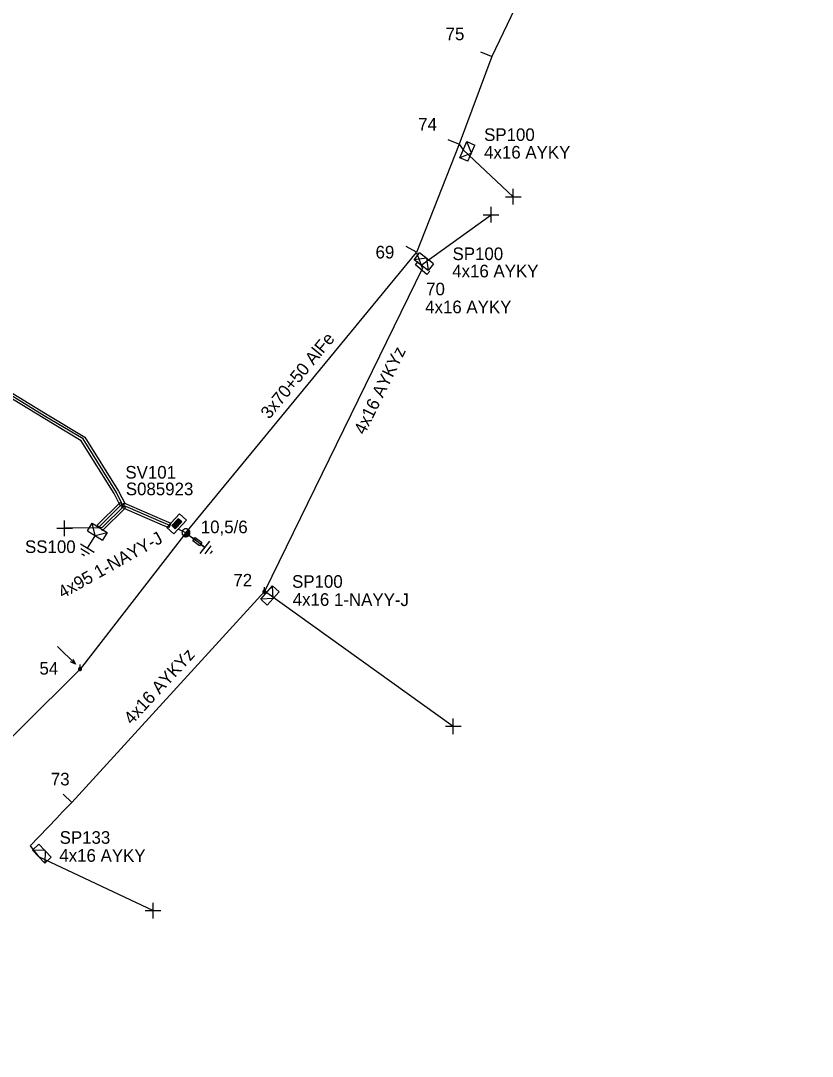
# Model space of a CAD drawing. Extents: x -788458 to -786145, y -1154772 to -1152372.
# Drawn here: x -787255.2 to -787192.5, y -1152639.6 to -1152557.4 of the extents above; entities that cross this region are included whole.
import ezdxf

# ---------------------------------------------------------------- set-up
doc = ezdxf.new("R2010")
doc.units = 0
for name, color, linetype in [('Vrstva 1', 7, 'Continuous'), ('Vrstva 12', 7, 'Continuous'), ('Vrstva 13', 7, 'Continuous'), ('Vrstva 14', 7, 'Continuous'), ('Vrstva 15', 7, 'Continuous'), ('Vrstva 16', 7, 'Continuous'), ('Vrstva 2', 7, 'Continuous'), ('Vrstva 20', 7, 'Continuous'), ('Vrstva 28', 7, 'Continuous'), ('Vrstva 29', 7, 'Continuous'), ('Vrstva 30', 7, 'Continuous'), ('Vrstva 31', 7, 'Continuous'), ('Vrstva 33', 7, 'Continuous'), ('Vrstva 34', 7, 'Continuous'), ('Vrstva 5', 7, 'Continuous'), ('Vrstva 52', 7, 'Continuous'), ('Vrstva 53', 7, 'Continuous'), ('Vrstva 54', 7, 'Continuous'), ('Vrstva 55', 7, 'Continuous'), ('Vrstva 59', 7, 'Continuous'), ('Vrstva 6', 7, 'Continuous'), ('Vrstva 8', 7, 'Continuous'), ('Vrstva 9', 7, 'Continuous')]:
    doc.layers.add(name, color=color, linetype=linetype)

# ---------------------------------------------------------------- blocks, each defined once
blk = doc.blocks.new('NN440')
at = {"layer": 'Vrstva 2'}
for points in [[(0.63, 0), (0.63, 0.06), (0.62, 0.13), (0.6, 0.19), (0.58, 0.25), (0.55, 0.31), (0.51, 0.37), (0.47, 0.42), (0.42, 0.46), (0.37, 0.51), (0.32, 0.54), (0.26, 0.57), (0.2, 0.59), (0.13, 0.61), (0.07, 0.62), (0, 0.63), (-0.06, 0.62), (-0.13, 0.61), (-0.19, 0.59), (-0.26, 0.57), (-0.31, 0.54), (-0.37, 0.51), (-0.42, 0.46), (-0.47, 0.42), (-0.51, 0.37), (-0.54, 0.31), (-0.57, 0.25), (-0.6, 0.19), (-0.62, 0.13), (-0.63, 0.06), (-0.63, 0), (-0.63, -0.07), (-0.62, -0.14), (-0.6, -0.2), (-0.57, -0.26), (-0.54, -0.32), (-0.51, -0.37), (-0.47, -0.43), (-0.42, -0.47), (-0.37, -0.51), (-0.31, -0.55), (-0.26, -0.58), (-0.19, -0.6), (-0.13, -0.62), (-0.06, -0.63), (0, -0.63), (0.07, -0.63), (0.13, -0.62), (0.2, -0.6), (0.26, -0.58), (0.32, -0.55), (0.37, -0.51), (0.42, -0.47), (0.47, -0.43), (0.51, -0.37), (0.55, -0.32), (0.58, -0.26), (0.6, -0.2), (0.62, -0.14), (0.63, -0.07), (0.63, 0)], [(-0.63, 0), (0.63, 0)], [(-0.6, -0.18), (0.57, -0.18)], [(-0.51, -0.32), (0.5, -0.32)], [(-0.37, -0.47), (0.35, -0.47)]]:
    blk.add_lwpolyline(points, dxfattribs=at)
blk = doc.blocks.new('NN565')
at = {"layer": 'Vrstva 2'}
for points in [[(0.015, 0.528), (0.015, 2.528)], [(0.157, 0.937), (0.015, 0.528), (-0.119, 0.937)]]:
    blk.add_lwpolyline(points, dxfattribs=at)
blk = doc.blocks.new('NN800')
at = {"layer": 'Vrstva 1'}
for points in [[(-0.442, 0.442), (0.442, -0.442)], [(-0.442, -0.442), (0.442, 0.442)]]:
    blk.add_lwpolyline(points, dxfattribs=at)
blk = doc.blocks.new('NN820')
at = {"layer": 'Vrstva 13'}
for points in [[(-0.003, 0.004), (-0.003, -1.049)], [(-0.165, -0.813), (0.165, -0.813)], [(-0.165, -1.473), (-0.165, -0.813)], [(0.165, -0.813), (0.165, -1.473)], [(0.165, -1.473), (-0.165, -1.473)], [(-0.003, -1.049), (-0.062, -0.926)], [(-0.003, -1.049), (0.057, -0.926)], [(-0.003, -1.473), (-0.003, -1.871)]]:
    blk.add_lwpolyline(points, dxfattribs=at)
blk = doc.blocks.new('NN620')
at = {"layer": 'Vrstva 8'}
for points in [[(0.752, 0.004), (-0.748, 0.004)], [(-0.748, 0.004), (-0.748, -0.746)], [(0.752, -0.746), (0.752, 0.004)], [(-0.748, -0.746), (0.752, -0.746)], [(0.368, -0.18), (-0.376, -0.18)], [(-0.376, -0.18), (-0.376, -0.558)], [(-0.376, -0.558), (0.368, -0.558)], [(0.321, -0.227), (-0.329, -0.227)], [(-0.329, -0.227), (-0.329, -0.51)], [(-0.329, -0.51), (0.321, -0.51)], [(0.274, -0.274), (-0.281, -0.274)], [(-0.281, -0.274), (-0.281, -0.463)], [(-0.281, -0.463), (0.274, -0.463)], [(0.227, -0.321), (-0.234, -0.321)], [(-0.234, -0.321), (-0.234, -0.416)], [(-0.234, -0.416), (0.227, -0.416)], [(-0.193, -0.369), (0.185, -0.369)], [(0.227, -0.416), (0.227, -0.321)], [(0.274, -0.463), (0.274, -0.274)], [(0.321, -0.51), (0.321, -0.227)], [(0.368, -0.558), (0.368, -0.18)]]:
    blk.add_lwpolyline(points, dxfattribs=at)
blk = doc.blocks.new('NN630')
at = {"layer": 'Vrstva 9'}
for points in [[(-0.003, -0.7), (-0.703, 0)], [(-0.703, -0.7), (-0.703, 0), (0.697, 0), (0.697, -0.7)], [(-0.703, -0.7), (0.697, -0.7)], [(-0.003, -0.7), (0.697, 0)]]:
    blk.add_lwpolyline(points, dxfattribs=at)
blk = doc.blocks.new('NN810')
at = {"layer": 'Vrstva 14'}
for points in [[(0.004, -0.64), (0.004, -1.89)], [(0.629, -1.89), (-0.621, -1.89)], [(0.388, -2.2), (-0.399, -2.2)], [(0.004, -2.515), (-0.124, -2.515)], [(0.137, -2.515), (0.004, -2.515)]]:
    blk.add_lwpolyline(points, dxfattribs=at)
blk = doc.blocks.new('NN500')
at = {"layer": 'Vrstva 2'}
for points in [[(0, -0.24), (0.02, -0.23), (0.05, -0.23), (0.07, -0.22), (0.09, -0.22), (0.12, -0.2), (0.14, -0.19), (0.16, -0.18), (0.17, -0.16), (0.19, -0.14), (0.2, -0.12), (0.21, -0.1), (0.22, -0.07), (0.23, -0.05), (0.23, -0.02), (0.23, 0), (0.23, 0.02), (0.23, 0.05), (0.22, 0.07), (0.21, 0.1), (0.2, 0.12), (0.19, 0.14), (0.17, 0.16), (0.16, 0.17), (0.14, 0.19), (0.12, 0.2), (0.09, 0.21), (0.07, 0.22), (0.05, 0.23), (0.02, 0.23), (0, 0.23), (-0.03, 0.23), (-0.05, 0.23), (-0.07, 0.22), (-0.1, 0.21), (-0.12, 0.2), (-0.14, 0.19), (-0.16, 0.17), (-0.18, 0.16), (-0.19, 0.14), (-0.2, 0.12), (-0.22, 0.1), (-0.22, 0.07), (-0.23, 0.05), (-0.23, 0.02), (-0.24, 0), (-0.23, -0.02), (-0.23, -0.05), (-0.22, -0.07), (-0.22, -0.1), (-0.2, -0.12), (-0.19, -0.14), (-0.18, -0.16), (-0.16, -0.18), (-0.14, -0.19), (-0.12, -0.2), (-0.1, -0.22), (-0.07, -0.22), (-0.05, -0.23), (-0.03, -0.23), (0, -0.24)], [(0, -0.24), (0.02, -0.23), (0.05, -0.23), (0.07, -0.22), (0.09, -0.22), (0.12, -0.2), (0.14, -0.19), (0.16, -0.18), (0.17, -0.16), (0.19, -0.14), (0.2, -0.12), (0.21, -0.1), (0.22, -0.07), (0.23, -0.05), (0.23, -0.02), (0.23, 0), (0.23, 0.02), (0.23, 0.05), (0.22, 0.07), (0.21, 0.1), (0.2, 0.12), (0.19, 0.14), (0.17, 0.16), (0.16, 0.17), (0.14, 0.19), (0.12, 0.2), (0.09, 0.21), (0.07, 0.22), (0.05, 0.23), (0.02, 0.23), (0, 0.23), (-0.03, 0.23), (-0.05, 0.23), (-0.07, 0.22), (-0.1, 0.21), (-0.12, 0.2), (-0.14, 0.19), (-0.16, 0.17), (-0.18, 0.16), (-0.19, 0.14), (-0.2, 0.12), (-0.22, 0.1), (-0.22, 0.07), (-0.23, 0.05), (-0.23, 0.02), (-0.24, 0), (-0.23, -0.02), (-0.23, -0.05), (-0.22, -0.07), (-0.22, -0.1), (-0.2, -0.12), (-0.19, -0.14), (-0.18, -0.16), (-0.16, -0.18), (-0.14, -0.19), (-0.12, -0.2), (-0.1, -0.22), (-0.07, -0.22), (-0.05, -0.23), (-0.03, -0.23), (0, -0.24)], [(0, -0.21), (0.02, -0.2), (0.04, -0.2), (0.06, -0.2), (0.08, -0.19), (0.1, -0.18), (0.12, -0.17), (0.14, -0.15), (0.15, -0.14), (0.16, -0.12), (0.18, -0.1), (0.19, -0.08), (0.19, -0.06), (0.2, -0.04), (0.2, -0.02), (0.2, 0), (0.2, 0.02), (0.2, 0.04), (0.19, 0.06), (0.19, 0.08), (0.18, 0.1), (0.16, 0.12), (0.15, 0.14), (0.14, 0.15), (0.12, 0.17), (0.1, 0.18), (0.08, 0.19), (0.06, 0.19), (0.04, 0.2), (0.02, 0.2), (0, 0.2), (-0.02, 0.2), (-0.04, 0.2), (-0.06, 0.19), (-0.08, 0.19), (-0.1, 0.18), (-0.12, 0.17), (-0.14, 0.15), (-0.15, 0.14), (-0.17, 0.12), (-0.18, 0.1), (-0.19, 0.08), (-0.2, 0.06), (-0.2, 0.04), (-0.21, 0.02), (-0.21, 0), (-0.21, -0.02), (-0.2, -0.04), (-0.2, -0.06), (-0.19, -0.08), (-0.18, -0.1), (-0.17, -0.12), (-0.15, -0.14), (-0.14, -0.15), (-0.12, -0.17), (-0.1, -0.18), (-0.08, -0.19), (-0.06, -0.2), (-0.04, -0.2), (-0.02, -0.2), (0, -0.21)], [(0, -0.18), (0.02, -0.18), (0.04, -0.17), (0.05, -0.17), (0.07, -0.16), (0.09, -0.15), (0.1, -0.14), (0.12, -0.13), (0.13, -0.12), (0.14, -0.1), (0.15, -0.09), (0.16, -0.07), (0.17, -0.05), (0.17, -0.04), (0.17, -0.02), (0.17, 0), (0.17, 0.02), (0.17, 0.04), (0.17, 0.05), (0.16, 0.07), (0.15, 0.09), (0.14, 0.1), (0.13, 0.12), (0.12, 0.13), (0.1, 0.14), (0.09, 0.15), (0.07, 0.16), (0.05, 0.17), (0.04, 0.17), (0.02, 0.17), (0, 0.18), (-0.02, 0.17), (-0.04, 0.17), (-0.06, 0.17), (-0.07, 0.16), (-0.09, 0.15), (-0.1, 0.14), (-0.12, 0.13), (-0.13, 0.12), (-0.14, 0.1), (-0.15, 0.09), (-0.16, 0.07), (-0.17, 0.05), (-0.17, 0.04), (-0.18, 0.02), (-0.18, 0), (-0.18, -0.02), (-0.17, -0.04), (-0.17, -0.05), (-0.16, -0.07), (-0.15, -0.09), (-0.14, -0.1), (-0.13, -0.12), (-0.12, -0.13), (-0.1, -0.14), (-0.09, -0.15), (-0.07, -0.16), (-0.06, -0.17), (-0.04, -0.17), (-0.02, -0.18), (0, -0.18)], [(0, -0.15), (0.01, -0.15), (0.03, -0.14), (0.04, -0.14), (0.06, -0.13), (0.07, -0.13), (0.08, -0.12), (0.1, -0.11), (0.11, -0.1), (0.12, -0.09), (0.13, -0.07), (0.13, -0.06), (0.14, -0.05), (0.14, -0.03), (0.14, -0.02), (0.14, 0), (0.14, 0.01), (0.14, 0.03), (0.14, 0.04), (0.13, 0.06), (0.13, 0.07), (0.12, 0.09), (0.11, 0.1), (0.1, 0.11), (0.08, 0.12), (0.07, 0.13), (0.06, 0.13), (0.04, 0.14), (0.03, 0.14), (0.01, 0.14), (0, 0.15), (-0.02, 0.14), (-0.03, 0.14), (-0.05, 0.14), (-0.06, 0.13), (-0.07, 0.13), (-0.09, 0.12), (-0.1, 0.11), (-0.11, 0.1), (-0.12, 0.09), (-0.13, 0.07), (-0.13, 0.06), (-0.14, 0.04), (-0.14, 0.03), (-0.15, 0.01), (-0.15, 0), (-0.15, -0.02), (-0.14, -0.03), (-0.14, -0.05), (-0.13, -0.06), (-0.13, -0.07), (-0.12, -0.09), (-0.11, -0.1), (-0.1, -0.11), (-0.09, -0.12), (-0.07, -0.13), (-0.06, -0.13), (-0.05, -0.14), (-0.03, -0.14), (-0.02, -0.15), (0, -0.15)], [(0, -0.12), (0.01, -0.12), (0.02, -0.11), (0.03, -0.11), (0.05, -0.11), (0.06, -0.1), (0.07, -0.09), (0.08, -0.09), (0.09, -0.08), (0.09, -0.07), (0.1, -0.06), (0.11, -0.05), (0.11, -0.04), (0.11, -0.02), (0.11, -0.01), (0.12, 0), (0.11, 0.01), (0.11, 0.02), (0.11, 0.04), (0.11, 0.05), (0.1, 0.06), (0.09, 0.07), (0.09, 0.08), (0.08, 0.09), (0.07, 0.09), (0.06, 0.1), (0.05, 0.11), (0.03, 0.11), (0.02, 0.11), (0.01, 0.12), (0, 0.12), (-0.01, 0.12), (-0.03, 0.11), (-0.04, 0.11), (-0.05, 0.11), (-0.06, 0.1), (-0.07, 0.09), (-0.08, 0.09), (-0.09, 0.08), (-0.1, 0.07), (-0.1, 0.06), (-0.11, 0.05), (-0.11, 0.04), (-0.12, 0.02), (-0.12, 0.01), (-0.12, 0), (-0.12, -0.01), (-0.12, -0.02), (-0.11, -0.04), (-0.11, -0.05), (-0.1, -0.06), (-0.1, -0.07), (-0.09, -0.08), (-0.08, -0.09), (-0.07, -0.09), (-0.06, -0.1), (-0.05, -0.11), (-0.04, -0.11), (-0.03, -0.11), (-0.01, -0.12), (0, -0.12)], [(0, -0.09), (0.01, -0.09), (0.02, -0.09), (0.03, -0.08), (0.03, -0.08), (0.04, -0.08), (0.05, -0.07), (0.06, -0.07), (0.06, -0.06), (0.07, -0.05), (0.07, -0.04), (0.08, -0.04), (0.08, -0.03), (0.08, -0.02), (0.09, -0.01), (0.09, 0), (0.09, 0.01), (0.08, 0.02), (0.08, 0.03), (0.08, 0.03), (0.07, 0.04), (0.07, 0.05), (0.06, 0.06), (0.06, 0.06), (0.05, 0.07), (0.04, 0.07), (0.03, 0.08), (0.03, 0.08), (0.02, 0.08), (0.01, 0.09), (0, 0.09), (-0.01, 0.09), (-0.02, 0.08), (-0.03, 0.08), (-0.04, 0.08), (-0.04, 0.07), (-0.05, 0.07), (-0.06, 0.06), (-0.07, 0.06), (-0.07, 0.05), (-0.08, 0.04), (-0.08, 0.03), (-0.08, 0.03), (-0.09, 0.02), (-0.09, 0.01), (-0.09, 0), (-0.09, -0.01), (-0.09, -0.02), (-0.08, -0.03), (-0.08, -0.04), (-0.08, -0.04), (-0.07, -0.05), (-0.07, -0.06), (-0.06, -0.07), (-0.05, -0.07), (-0.04, -0.08), (-0.04, -0.08), (-0.03, -0.08), (-0.02, -0.09), (-0.01, -0.09), (0, -0.09)], [(0, -0.06), (0, -0.06), (0.01, -0.06), (0.02, -0.05), (0.02, -0.05), (0.03, -0.05), (0.03, -0.05), (0.04, -0.04), (0.04, -0.04), (0.05, -0.03), (0.05, -0.03), (0.05, -0.02), (0.05, -0.02), (0.05, -0.01), (0.06, -0.01), (0.06, 0), (0.06, 0.01), (0.05, 0.01), (0.05, 0.02), (0.05, 0.02), (0.05, 0.03), (0.05, 0.03), (0.04, 0.04), (0.04, 0.04), (0.03, 0.05), (0.03, 0.05), (0.02, 0.05), (0.02, 0.05), (0.01, 0.06), (0, 0.06), (0, 0.06), (-0.01, 0.06), (-0.01, 0.06), (-0.02, 0.05), (-0.02, 0.05), (-0.03, 0.05), (-0.03, 0.05), (-0.04, 0.04), (-0.04, 0.04), (-0.05, 0.03), (-0.05, 0.03), (-0.05, 0.02), (-0.06, 0.02), (-0.06, 0.01), (-0.06, 0.01), (-0.06, 0), (-0.06, -0.01), (-0.06, -0.01), (-0.06, -0.02), (-0.05, -0.02), (-0.05, -0.03), (-0.05, -0.03), (-0.04, -0.04), (-0.04, -0.04), (-0.03, -0.05), (-0.03, -0.05), (-0.02, -0.05), (-0.02, -0.05), (-0.01, -0.06), (-0.01, -0.06), (0, -0.06)], [(0, -0.03), (0, -0.03), (0, -0.03), (0.01, -0.03), (0.01, -0.03), (0.01, -0.02), (0.02, -0.02), (0.02, -0.02), (0.02, -0.02), (0.02, -0.02), (0.02, -0.01), (0.02, -0.01), (0.03, -0.01), (0.03, -0.01), (0.03, 0), (0.03, 0), (0.03, 0), (0.03, 0.01), (0.03, 0.01), (0.02, 0.01), (0.02, 0.01), (0.02, 0.02), (0.02, 0.02), (0.02, 0.02), (0.02, 0.02), (0.01, 0.02), (0.01, 0.02), (0.01, 0.03), (0, 0.03), (0, 0.03), (0, 0.03), (0, 0.03), (-0.01, 0.03), (-0.01, 0.03), (-0.01, 0.02), (-0.02, 0.02), (-0.02, 0.02), (-0.02, 0.02), (-0.02, 0.02), (-0.02, 0.02), (-0.03, 0.01), (-0.03, 0.01), (-0.03, 0.01), (-0.03, 0.01), (-0.03, 0), (-0.03, 0), (-0.03, 0), (-0.03, -0.01), (-0.03, -0.01), (-0.03, -0.01), (-0.03, -0.01), (-0.02, -0.02), (-0.02, -0.02), (-0.02, -0.02), (-0.02, -0.02), (-0.02, -0.02), (-0.01, -0.03), (-0.01, -0.03), (-0.01, -0.03), (0, -0.03), (0, -0.03)], [(0.23, 0), (0.7, 0)]]:
    blk.add_lwpolyline(points, dxfattribs=at)
blk = doc.blocks.new('NN510')
at = {"layer": 'Vrstva 2'}
blk.add_lwpolyline([(0.001, 0.002), (0.001, 0.939)], dxfattribs=at)
blk = doc.blocks.new('NN515')
at = {"layer": 'Vrstva 2'}
for points in [[(-0.59, 0.176), (0.591, 0.176)], [(-0.59, 0.176), (-0.59, -0.179)], [(0.591, 0.176), (0.591, -0.179)]]:
    blk.add_lwpolyline(points, dxfattribs=at)

msp = doc.modelspace()

# ---------------------------------------------------------------- linework, layer by layer
at = {"layer": 'Vrstva 1'}
for points in [[(-787192.479, -1152515.179), (-787204.31, -1152531.45), (-787211.57, -1152547.04), (-787217.9, -1152560.27), (-787220.49, -1152567.22), (-787223.86, -1152575.79)], [(-787242.14, -1152598.03), (-787223.86, -1152575.79)], [(-787242.14, -1152598.03), (-787250.54, -1152608.84), (-787264.71, -1152622.95), (-787283.97, -1152642.09), (-787296.85, -1152653.64), (-787309.78, -1152670.5), (-787318.12, -1152687.04), (-787327.56, -1152703.03)]]:
    msp.add_lwpolyline(points, dxfattribs=at)
at = {"layer": 'Vrstva 20'}
for points in [[(-787271.09, -1152586.262), (-787267.524, -1152586.809), (-787263.303, -1152586.421), (-787257.997, -1152585.702), (-787253.267, -1152588.579), (-787250.156, -1152590.443), (-787247.485, -1152594.732), (-787246.971, -1152595.75), (-787247.329, -1152595.93), (-787247.835, -1152594.928), (-787250.444, -1152590.737), (-787253.473, -1152588.921), (-787258.083, -1152586.118), (-787263.257, -1152586.819), (-787267.536, -1152587.211), (-787271.15, -1152586.658)], [(-787249.182, -1152597.437), (-787247.362, -1152595.627), (-787246.938, -1152596.053), (-787248.758, -1152597.863)], [(-787247.071, -1152595.656), (-787244.02, -1152596.977), (-787243.344, -1152597.277), (-787243.506, -1152597.642), (-787244.18, -1152597.343), (-787247.229, -1152596.024)]]:
    msp.add_lwpolyline(points, close=True, dxfattribs=at)
at = {"layer": 'Vrstva 5'}
for points in [[(-787223.86, -1152575.79), (-787223.5, -1152576.81)], [(-787223.38, -1152577.04), (-787223.5, -1152576.81)], [(-787243.425, -1152597.46), (-787244.1, -1152597.16), (-787246.73, -1152596.022), (-787247.051, -1152595.883), (-787248.793, -1152597.615), (-787248.97, -1152597.65), (-787248.941, -1152597.48), (-787247.197, -1152595.746), (-787247.345, -1152595.455), (-787247.66, -1152594.83), (-787250.3, -1152590.59), (-787253.37, -1152588.75), (-787258.04, -1152585.91)], [(-787242.14, -1152598.03), (-787242.768, -1152597.751)]]:
    msp.add_lwpolyline(points, dxfattribs=at)
at = {"layer": 'Vrstva 52'}
for points in [[(-787220.49, -1152567.22), (-787220.15, -1152567.65)], [(-787223.38, -1152577.04), (-787235.92, -1152602.7)], [(-787251.19, -1152619.42), (-787235.92, -1152602.7)], [(-787251.19, -1152619.42), (-787251.916, -1152620.174), (-787252.38, -1152620.656), (-787254.49, -1152622.85), (-787253.82, -1152623.72)]]:
    msp.add_lwpolyline(points, dxfattribs=at)
at = {"layer": 'Vrstva 59'}
for points in [[(-787220.15, -1152567.65), (-787216.19, -1152571.38)], [(-787223.5, -1152576.81), (-787217.951, -1152572.811)], [(-787248.97, -1152597.65), (-787251.76, -1152597.678)], [(-787235.74, -1152602.77), (-787220.94, -1152613.38)], [(-787253.82, -1152623.72), (-787244.75, -1152628)]]:
    msp.add_lwpolyline(points, dxfattribs=at)
at = {"layer": 'Vrstva 8'}
msp.add_lwpolyline([(-787235.92, -1152602.7), (-787235.74, -1152602.77)], dxfattribs=at)

# ---------------------------------------------------------------- block references
at = {"layer": 'Vrstva 13'}
for name, p, rotation in [('NN510', (-787217.9, -1152560.27), 67.2519388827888), ('NN510', (-787220.49, -1152567.22), 67.76382501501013), ('NN510', (-787223.86, -1152575.79), 59.814683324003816), ('NN515', (-787223.38, -1152577.04), 139.86833344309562), ('NN565', (-787250.54, -1152608.84), 45.371777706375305), ('NN510', (-787251.19, -1152619.42), 45.8243416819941)]:
    msp.add_blockref(name, p, dxfattribs=dict(at, rotation=rotation))
at = {"layer": 'Vrstva 13', "xscale": 0.5}
for name, p, yscale, rotation in [('NN440', (-787242.14, -1152598.03), 0.5000000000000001, 52.150678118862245), ('NN500', (-787235.92, -1152602.7), 0.5, 90), ('NN500', (-787250.54, -1152608.84), 0.5, 90)]:
    msp.add_blockref(name, p, dxfattribs=dict(at, yscale=yscale, rotation=rotation))
at = {"layer": 'Vrstva 15'}
for p, rotation in [((-787248.97, -1152597.65), -31.715142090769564), ((-787242.14, -1152598.03), 52.150678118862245)]:
    msp.add_blockref('NN810', p, dxfattribs=dict(at, rotation=rotation))
at = {"layer": 'Vrstva 16', "rotation": 52.150678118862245}
msp.add_blockref('NN820', (-787242.14, -1152598.03), dxfattribs=at)
at = {"layer": 'Vrstva 28', "rotation": -132.96669666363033}
msp.add_blockref('NN620', (-787242.604, -1152597.575), dxfattribs=at)
at = {"layer": 'Vrstva 31'}
for p, rotation in [((-787220.15, -1152567.65), 66.80140950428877), ((-787223.5, -1152576.81), 141.98105749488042), ((-787248.97, -1152597.65), -31.715142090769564), ((-787235.74, -1152602.77), 47.815556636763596), ((-787253.82, -1152623.72), 133.5004529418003)]:
    msp.add_blockref('NN630', p, dxfattribs=dict(at, rotation=rotation))
at = {"layer": 'Vrstva 34'}
for p, rotation in [((-787216.19, -1152571.38), 44.99999995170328), ((-787217.951, -1152572.811), 45), ((-787251.76, -1152597.678), 45), ((-787220.94, -1152613.38), 44.99999995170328), ((-787244.75, -1152628), 45)]:
    msp.add_blockref('NN800', p, dxfattribs=dict(at, rotation=rotation))

# ---------------------------------------------------------------- texts
at = {"layer": 'Vrstva 12'}
msp.add_text('10,5/6', height=1, dxfattribs=at).set_placement((-787240.965, -1152598.068))
at = {"layer": 'Vrstva 14'}
for s, p in [('75', (-787221.552, -1152558.965)), ('74', (-787223.724, -1152566.129)), ('69', (-787227.106, -1152576.274)), ('70', (-787223.097, -1152579.197)), ('72', (-787238.382, -1152602.293)), ('54', (-787253.754, -1152609.284)), ('73', (-787252.853, -1152618.07))]:
    msp.add_text(s, height=1, dxfattribs=at).set_placement(p)
at = {"layer": 'Vrstva 2'}
msp.add_text('3x70+50 AlFe', height=1, rotation=50.637, dxfattribs=at).set_placement((-787235.539, -1152589.075))
at = {"layer": 'Vrstva 29'}
msp.add_text('S085923', height=1, dxfattribs=at).set_placement((-787246.908, -1152595.054))
at = {"layer": 'Vrstva 30'}
msp.add_text('SV101', height=1, dxfattribs=at).set_placement((-787246.942, -1152593.734))
at = {"layer": 'Vrstva 33'}
for s, p in [('SP100', (-787218.5, -1152566.957)), ('SP100', (-787221.002, -1152576.404)), ('SS100', (-787254.901, -1152599.637)), ('SP100', (-787233.727, -1152602.396)), ('SP133', (-787252.155, -1152622.699))]:
    msp.add_text(s, height=1, dxfattribs=at).set_placement(p)
at = {"layer": 'Vrstva 53'}
for rotation, p in [(63.955, (-787227.976, -1152590.322)), (47.595, (-787246.432, -1152613.303))]:
    msp.add_text('4x16 AYKYz', height=1, rotation=rotation, dxfattribs=at).set_placement(p)
at = {"layer": 'Vrstva 54'}
msp.add_text('4x16 AYKY', height=1, dxfattribs=at).set_placement((-787218.5, -1152568.353))
msp.add_text('4x16 AYKY', height=1, rotation=359.885, dxfattribs=at).set_placement((-787252.181, -1152624.122))
at = {"layer": 'Vrstva 55'}
msp.add_text('4x16 1-NAYY-J', height=1, rotation=359.823, dxfattribs=at).set_placement((-787233.677, -1152603.819))
at = {"layer": 'Vrstva 6'}
for p in [(-787221.028, -1152577.774), (-787223.175, -1152580.619)]:
    msp.add_text('4x16 AYKY', height=1, dxfattribs=at).set_placement(p)
msp.add_text('4x95 1-NAYY-J', height=1, rotation=29.358, dxfattribs=at).set_placement((-787251.922, -1152603.274))

doc.saveas('drawing.dxf')
